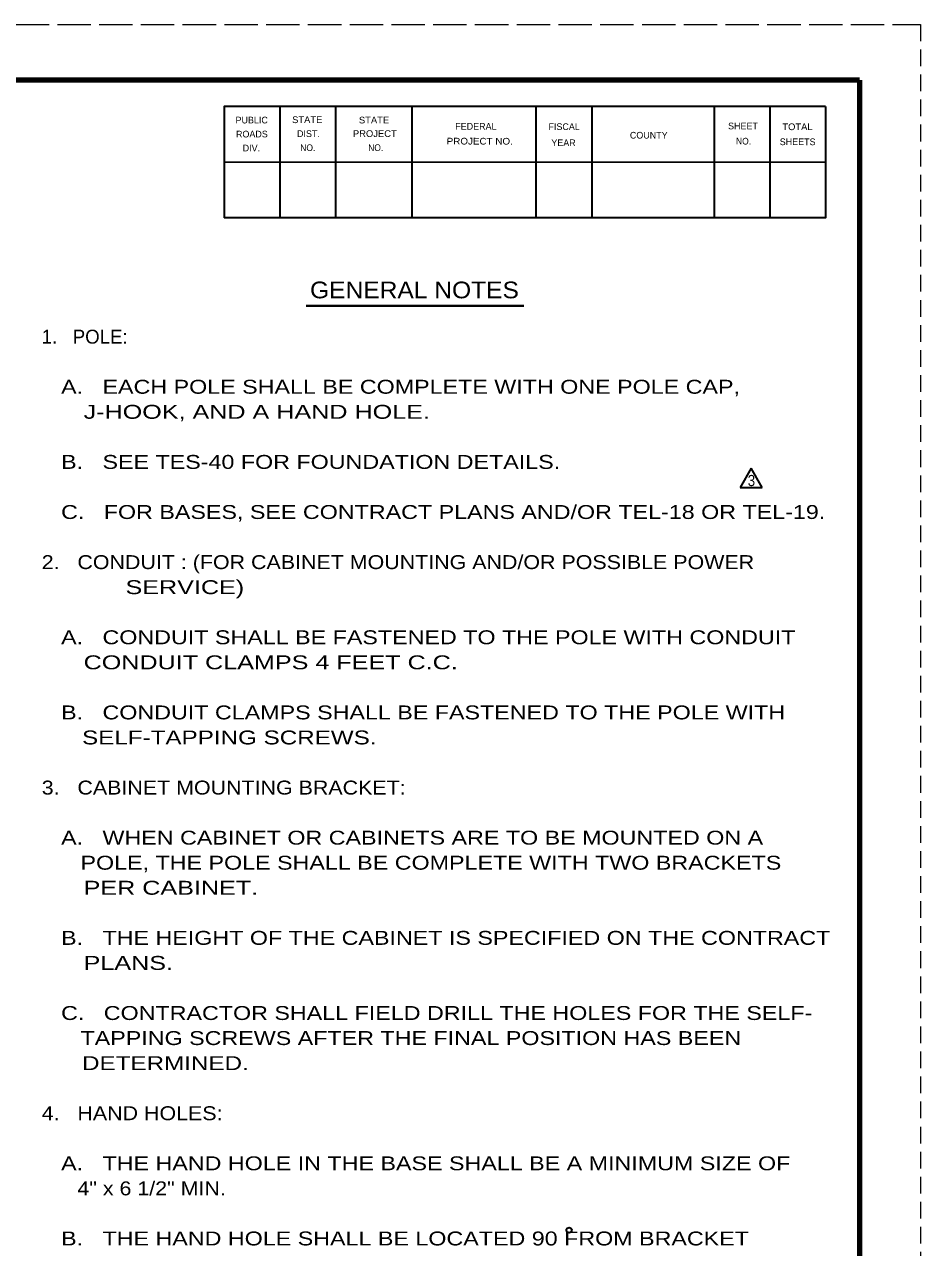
# Model space of a CAD drawing. Extents: x -1 to 679, y 1 to 441.
# Drawn here: x 518.5 to 679.4, y 221.2 to 440.9 of the extents above; entities that cross this region are included whole.
import ezdxf

# ---------------------------------------------------------------- set-up
doc = ezdxf.new("R2010")
doc.units = 0
doc.linetypes.add('LONG_DASHED', pattern=[7.5, 6, -1.5])
doc.linetypes.add('MEDIUM_DASHED', pattern=[4.5, 3, -1.5])
doc.layers.add('1', color=7, linetype='Continuous', lineweight=13)
doc.layers.add('61', color=7, linetype='Continuous', lineweight=35)

msp = doc.modelspace()

# ---------------------------------------------------------------- linework, layer by layer
at = {"layer": '1', "linetype": 'MEDIUM_DASHED'}
msp.add_line((679.412, 440.866), (679.392, 0.846), dxfattribs=at)
at = {"layer": '1', "lineweight": 40}
msp.add_line((569.075, 390.298), (608.197, 390.298), dxfattribs=at)
at = {"layer": '1', "lineweight": 35}
for p, q in [((648.99, 361.132), (646.99, 357.668)), ((650.99, 357.668), (648.99, 361.132)), ((646.99, 357.668), (650.99, 357.668))]:
    msp.add_line(p, q, dxfattribs=at)
msp.add_circle((616.292, 224.267), 0.477, dxfattribs=at)
at = {"layer": '61', "linetype": 'LONG_DASHED', "lineweight": 13}
msp.add_line((-0.608, 440.866), (679.412, 440.866), dxfattribs=at)
at = {"layer": '61', "lineweight": 158}
msp.add_line((668.432, 430.866), (668.452, 10.826), dxfattribs=at)
at = {"layer": '61'}
for p, q in [((564.352, 426.106), (564.352, 406.106)), ((574.352, 426.106), (574.352, 406.106)), ((588.032, 426.106), (588.032, 406.106)), ((610.352, 426.106), (610.352, 406.106)), ((620.352, 426.106), (620.352, 406.106)), ((642.332, 426.126), (642.332, 406.126)), ((652.332, 426.126), (652.332, 406.126)), ((662.352, 416.086), (554.332, 416.106))]:
    msp.add_line(p, q, dxfattribs=at)
at = {"layer": '61', "lineweight": 158}
msp.add_lwpolyline([(668.432, 430.866), (29.392, 430.866), (29.392, 10.846)], dxfattribs=at)
at = {"layer": '61'}
for points in [[(662.332, 426.126), (554.352, 426.106), (554.352, 406.106)], [(662.332, 426.126), (662.332, 406.126), (554.352, 406.106)]]:
    msp.add_lwpolyline(points, dxfattribs=at)

# ---------------------------------------------------------------- texts
at = {"layer": '1'}
for s, height, width, p in [('GENERAL NOTES', 3, 1.1, (569.768, 391.675)), ('   A.   EACH POLE SHALL BE COMPLETE WITH ONE POLE CAP,', 2.5, 1.25, (521.582, 374.531)), ('      J-HOOK, AND A HAND HOLE.', 2.5, 1.35, (521.582, 370.031)), ('   B.   SEE TES-40 FOR FOUNDATION DETAILS.', 2.5, 1.25, (521.582, 361.031)), ('3', 2, 0.9, (648.37, 357.938)), ('   C.   FOR BASES, SEE CONTRACT PLANS AND/OR TEL-18 OR TEL-19.', 2.5, 1.25, (521.582, 352.031)), ('2.   CONDUIT : (FOR CABINET MOUNTING AND/OR POSSIBLE POWER', 2.5, 1.15, (521.582, 343.031)), ('            SERVICE)', 2.5, 1.35, (521.582, 338.531)), ('   A.   CONDUIT SHALL BE FASTENED TO THE POLE WITH CONDUIT', 2.5, 1.25, (521.582, 329.531)), ('      CONDUIT CLAMPS 4 FEET C.C.', 2.5, 1.35, (521.582, 325.031)), ('   B.   CONDUIT CLAMPS SHALL BE FASTENED TO THE POLE WITH', 2.5, 1.25, (521.582, 316.031)), ('      SELF-TAPPING SCREWS.', 2.5, 1.3, (521.582, 311.531)), ('3.   CABINET MOUNTING BRACKET:', 2.5, 1.15, (521.582, 302.531)), ('   A.   WHEN CABINET OR CABINETS ARE TO BE MOUNTED ON A', 2.5, 1.25, (521.582, 293.531)), ('      POLE, THE POLE SHALL BE COMPLETE WITH TWO BRACKETS', 2.5, 1.25, (521.582, 289.031)), ('      PER CABINET.', 2.5, 1.35, (521.582, 284.531)), ('   B.   THE HEIGHT OF THE CABINET IS SPECIFIED ON THE CONTRACT', 2.5, 1.25, (521.582, 275.531)), ('      PLANS.', 2.5, 1.35, (521.582, 271.031)), ('   C.   CONTRACTOR SHALL FIELD DRILL THE HOLES FOR THE SELF-', 2.5, 1.25, (521.582, 262.031)), ('      TAPPING SCREWS AFTER THE FINAL POSITION HAS BEEN', 2.5, 1.25, (521.582, 257.531)), ('      DETERMINED.', 2.5, 1.3, (521.582, 253.031)), ('4.   HAND HOLES:', 2.5, 1.15, (521.582, 244.031)), ('   A.   THE HAND HOLE IN THE BASE SHALL BE A MINIMUM SIZE OF', 2.5, 1.25, (521.582, 235.031)), ('      4" x 6 1/2" MIN.', 2.5, 1.15, (521.582, 230.531)), ('   B.   THE HAND HOLE SHALL BE LOCATED 90 FROM BRACKET', 2.5, 1.25, (521.582, 221.531))]:
    msp.add_text(s, height=height, dxfattribs=dict(at, width=width)).set_placement(p)
msp.add_text('1.   POLE:', height=2.5, dxfattribs=at).set_placement((521.582, 383.531))
at = {"layer": '61'}
for s, rotation, p in [('PUBLIC', 0.033, (556.392, 423.086)), ('DIST.', 0.056, (567.432, 420.646)), ('FEDERAL', 0.007, (595.852, 421.966)), ('FISCAL', 359.942, (612.592, 421.906)), ('SHEET', 0.059, (644.852, 422.026)), ('ROADS', 0.124, (556.472, 420.566)), ('YEAR', 0.105, (613.112, 419.006)), ('COUNTY', 0.069, (627.212, 420.366)), ('SHEETS', 359.959, (654.132, 419.186)), ('DIV.', 359.932, (557.672, 418.066))]:
    msp.add_text(s, height=1.201, rotation=rotation, dxfattribs=at).set_placement(p)
for s, rotation, width, p in [('STATE', 0.059, 1.05, (566.552, 423.146)), ('STATE', 0.059, 1.05, (578.552, 423.086)), ('PROJECT', 359.908, 1.05, (577.472, 420.666)), ('TOTAL', 359.926, 1.05, (654.592, 421.886)), ('PROJECT NO.', 359.922, 1.1, (594.312, 419.306)), ('NO.', 359.852, 0.95, (646.272, 419.306)), ('NO.', 359.852, 0.95, (568.012, 418.126)), ('NO.', 0.225, 0.95, (580.212, 418.126))]:
    msp.add_text(s, height=1.201, rotation=rotation, dxfattribs=dict(at, width=width)).set_placement(p)

doc.saveas('drawing.dxf')
